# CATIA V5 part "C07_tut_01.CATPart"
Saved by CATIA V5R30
Part number: Part1
Bounding box of the stored display mesh (mm): x -150 to 150, y -150 to 150, z -127.513 to 0
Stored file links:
  D:\PROJECTS\CATIA V56R 2020\Resources\c07\C07_tut_01.CATPart
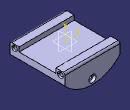
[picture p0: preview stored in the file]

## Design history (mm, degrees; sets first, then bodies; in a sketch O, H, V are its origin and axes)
Body1 (main body)
  Sketch1 on zx-plane, origin (0, 0, 0), H (-1, 0, 0), V (0, 0, 1)
    point P1 (-150, 0)
    line L1 (-150, 0) -> (150, 0)
    point P2 (150, 0)
    line L2 (150, 0) -> (150, -60)
    point P3 (150, -60)
    point P4 (-150, -60)
    point P5 (-150, 0)
    line L3 (-150, 0) -> (-150, -60)
    arc A1 centre (0, 72.2876) radius 200 from (150, -60) to (-150, -60) cw
    point P7 (0, -127.7124)
    length L1 = 300
    length L2 = 60
    radius A1 = 200
    horizontal: L1 H
    vertical: L2 V
    symmetry: P1 P2 V, P3 P4 V, P2 P5 V, L2 L3 V
    coincidence: L1 H, A1 P7, P7 V, P1 P5
  Pad1: profile Sketch1, direction (0, 1, 0), length 150, mirrored extent
  Sketch2 on yz-plane, origin (0, 0, 0), H (0, 1, 0), V (0, 0, 1)
    line L1 (100, 0) -> (-100, 0)
    reference projected line E1 (-150, 0) -> (150, 0) from edge [face of Pad1 from Sketch1.L3 | face of Pad1 from Sketch1.L1]
    line L2 (-100, 0) -> (-100, -25)
    line L3 (-100, -25) -> (100, -25)
    line L4 (100, -25) -> (100, 0)
    length L1 = 200
    length L4 = 25
    distance V L4 = 100
    horizontal: L1 H, L3 H
    coincidence: L1 E1
    vertical: L2 V, L4 V
  Pocket1: profile Sketch2, direction (-1, 0, 0), length 150, mirrored extent
  Fillet1: radius 10, on edge [start face of Pad1 | face of Pad1 from Sketch1.L1]; edge [face of Pad1 from Sketch1.L1 | end face of Pad1]
  Sketch3 on yz-plane, origin (0, 0, 0), H (0, 1, 0), V (0, 0, 1)
    point P1 (-125, -20)
    point P2 (125, -20)
    reference projected line E1 (150, 0) -> (150, -60) from edge [face of Pad1 from Sketch1.L3 | end face of Pad1]
    reference projected line E2 (-150, 0) -> (150, 0) from edge [face of Pad1 from Sketch1.L3 | face of Pad1 from Sketch1.L1]
    distance P2 E1 = 25
    distance P2 E2 = 20
    symmetry: P1 P2 V
  Sketch4 on face of Pad1 from Sketch1.L3, origin (150, 125, -20), H (0, 1, 0), V (0, 0, 1)
    point P1 (0, 0)
    reference projected point E1 (0, 0) from Sketch3.P2
    coincidence: E1 P1
  Hole1: placed by Sketch4, at (150, 125, -20) direction (-1, 0, 0), diameter 20, through (limit type 3), countersink depth 5, countersink angle 90
  Sketch5 on face of Pad1 from Sketch1.L3, origin (150, -125, -20), H (0, 1, 0), V (0, 0, 1)
    point P1 (0, 0)
    reference projected point E1 (0, 0) from Sketch3.P1
    coincidence: E1 P1
  Hole2: placed by Sketch5, at (150, -125, -20) direction (-1, 0, 0), diameter 20, through (limit type 3), countersink depth 5, countersink angle 90
  Sketch6 on zx-plane, origin (0, 0, 0), H (-1, 0, 0), V (0, 0, 1)
    point P1 (0, -100)
    distance P1 H = 100
    coincidence: P1 V
  Sketch7 on end face of Pad1, origin (0, 150, -100), H (1, 0, 0), V (0, 0, -1)
    point P1 (0, 0)
    reference projected point E1 (0, 0) from Sketch6.P1
    coincidence: E1 P1
  Hole3: placed by Sketch7, at (0, 150, -100) direction (0, -1, 0), diameter 20, through (limit type 3), counterbore diameter 40, counterbore depth 15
